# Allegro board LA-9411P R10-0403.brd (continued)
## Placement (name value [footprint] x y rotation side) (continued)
CH25  -  [C_0402]  206.75 72.14 315 top
CH26  -  [C_0603]  208.25 84.93 45 top
CH27  -  [C_0402]  211.6 71.87 315 top
CH28  -  [C_0805]  202.9 86.85 225 top
CH29  -  [C_0402]  209.92 68.98 135 top
CH30  -  [C_0402]  207.61 69.22 315 top
CH31  -  [C_0603]  200.86 78.49 315 top
CH32  -  [C_0603]  196.21 83.14 135 top
CH33  -  [C_0603]  195 81.92 135 top
CH34  -  [C_0402]  205.13 71.71 315 top
CH35  -  [C_0402]  210.99 72.48 135 top
CH36  -  [C_0402]  207.93 79.97 315 top
CH37  -  [C_0402]  207.31 74.01 135 top
CH38  -  [C_0603]  209.01 92.86 135 bottom
CH39  -  [C_0402]  201.92 66.02 135 top
CH40  -  [C_0402]  212.3 63.19 135 top
CH41  -  [C_0603]  205.26 81.24 135 top
CH42  -  [C_0402]  207.61 75.96 315 top
CH43  -  [C_0402]  208.66 70.24 135 top
CH44  -  [C_0402]  215.18 60.46 315 bottom
CH45  -  [C_0402]  209.38 71.86 135 top
CH46  -  [C_0402]  204.98 69.63 225 top
CH47  -  [C_0402]  215.47 77.24 45 top
CH48  -  [C_0402]  211.35 68.8 135 top
CH49  -  [C_0402]  203.78 70.93 315 top
CH50  -  [C_0402]  205.09 75.13 45 top
CH51  -  [C_0402]  209.83 61.91 225 top
CH52  -  [C_0603]  195.13 83.21 135 bottom
CH53  -  [C_0402]  212.27 80.59 135 top
CH54  -  [C_0402]  207.29 67.35 135 top
CH55  -  [C_0402]  211.58 55.31 225 bottom
CH56  -  [C_0402]  210.95 55.93 225 bottom
CH57  -  [C_0402]  210.32 56.56 225 bottom
CH58  -  [C_0402]  214.86 78.05 135 top
CH59  -  [C_0402]  202.62 67.19 45 top
CH60  -  [C_0402]  197.84 67.61 225 top
CH61  -  [C_0402]  198.72 69.29 315 top
CH62  -  [C_0402]  198.42 68.35 315 top
CH63  -  [C_0603]  211.3 88.21 135 bottom
CH64  -  [C_0402]  211.61 87.04 45 bottom
CH65  -  [C_0402]  208.49 77.42 135 top
CH66  -  [C_0402]  217.44 63.07 45 top
CH67  -  [C_0402]  210.03 75.69 315 top
CH68  -  [C_0402]  213.54 80.54 315 top
CH69  -  [C_0402]  209.78 73.79 135 top
CH70  -  [C_0402]  212.91 79.91 315 top
CH71  -  [C_0402]  211.2 75.94 45 top
CH72  -  [C_0402]  212.24 73.49 135 top
CH73  -  [C_0402]  211.26 70.15 135 top
CH74  -  [C_0402]  212.98 72.95 315 top
CH75  -  [C_0402]  215.8 68.15 225 top
CH76  -  [C_0402]  225.73 72.46 135 bottom
CH77  -  [C_0402]  225.22 67.77 225 bottom
CH78  -  [C_0402]  225.22 70.43 135 bottom
CH79  -  [C_0402]  227.12 66.02 315 top
CH80  -  [C_0402]  227.08 67.52 315 top
CLIP1  -  [EMI-110X138]  145.4 13.22 270 bottom
CMOS1  -  [SHORTPADS]  210.85 58.98 315 top
CV1  -  [C_0402]  217.6 109.44 270 top
CV2  -  [C_0402]  218.61 109.45 270 top
CV3  -  [C_0402]  217.98 105.99 270 top
CV4  -  [C_0402]  216.96 105.98 270 top
CV5  -  [C_0402]  213.66 105.98 270 top
CV6  -  [C_0402]  214.68 105.99 270 top
CV7  -  [C_0402]  213.66 109.44 270 top
CV8  -  [C_0402]  212.64 109.44 270 top
CV9  -  [C_0402]  211.37 105.99 270 top
CV10  -  [C_0402]  210.36 105.98 270 top
CV11  -  [C_0402]  210.36 109.44 270 top
CV12  -  [C_0402]  209.34 109.44 270 top
CV13  -  [C_0402]  195.5 161.92 180 top
CV14  -  [C_0402]  208.1 105.99 270 top
CV15  -  [C_0402]  207.06 105.98 270 top
CV16  -  [C_0402]  207.06 109.44 270 top
CV17  -  [C_0402]  206.04 109.44 270 top
CV18  -  [C_0402]  194.59 160.91 0 top
CV19  -  [C_0402]  216.98 158.13 180 top
CV20  -  [C_0402]  216.06 159.14 0 top
CV21  -  [C_0402]  210.42 151.83 90 top
CV22  -  [C_0402]  209.41 152.74 270 top
CV23  -  [C_0402]  216.06 163.21 0 top
CV24  -  [C_0402]  216.98 162.19 180 top
CV25  -  [C_0402]  196.45 170.12 90 top
CV26  -  [C_0402]  197.47 171.03 270 top
CV27  -  [C_0402]  206.36 152.74 270 top
CV28  -  [C_0402]  205.34 151.83 90 top
CV29  -  [C_0402]  227.95 170.12 90 bottom
CV30  -  [C_0402]  228.96 171.03 270 bottom
CV31  -  [C_0402]  214.99 170.12 90 bottom
CV32  -  [C_0402]  217.03 171.03 270 bottom
CV33  -  [C_0402]  231.25 152.74 270 top
CV34  -  [C_0402]  230.23 151.83 90 top
CV35  -  [C_0402]  216.98 154.06 180 top
CV36  -  [C_0402]  216.06 155.08 0 top
CV37  -  [C_0402]  236.08 150.2 270 bottom
CV38  -  [C_0402]  237.09 149.29 90 bottom
CV39  -  [C_0402]  227.69 170.12 90 top
CV40  -  [C_0402]  226.68 171.03 270 top
CV41  -  [C_0603]  184.45 109.6 180 top
CV42  -  [C_0603]  184.7 111.39 180 bottom
CV43  -  [C_0603]  183.85 132.47 180 bottom
CV44  -  [C_0603]  183.75 131.97 180 top
CV45  -  [C_0603]  213.88 171.51 270 bottom
CV46  -  [C_0603]  200.1 170.27 0 top
CV47  -  [C_0603]  232.77 170.13 90 bottom
CV48  -  [C_0603]  233.03 170.13 90 top
CV49  -  [C_0402]  227.99 129.22 180 top
CV50  -  [C_0402]  228.59 128.35 270 top
CV51  -  [C_0402]  229.47 119.21 270 top
CV52  -  [C_0402]  248.83 116.98 0 top
CV53  -  [C_0402]  246.95 111.14 180 top
CV54  -  [C_0402]  240.9 127.85 270 top
CV55  -  [C_0402]  227.04 127.26 180 top
CV56  -  [C_0603]  239.63 127.84 270 top
CV57  -  [C_0402]  249.74 110.38 180 top
CV58  -  [C_0402]  241.36 113.68 180 top
CV59  -  [C_0603]  241.35 112.41 180 top
CV60  -  [C_0402]  227.16 137.3 0 top
CV61  -  [C_0402]  227.09 136.07 0 top
CV62  -  [C_0603]  239.7 135.01 0 bottom
CV63  -  [C_0402]  227.44 119.21 270 top
CV64  -  [C_0603]  235.31 115.14 270 top
CV65  -  [C_0402]  228.46 119.21 270 top
CV66  -  [C_0402]  212.2 123.02 270 top
CV67  -  [C_0402]  216.14 125.22 0 top
CV68  -  [C_0402]  215.85 123.9 270 top
CV69  -  [C_0402]  232.59 121.05 90 top
CV70  -  [C_0402]  217.91 125.09 0 top
CV71  -  [C_0402]  217.92 126.01 90 top
CV72  -  [C_0402]  214.97 123.88 180 top
CV73  -  [C_0603]  208.9 125.93 90 top
CV74  -  [C_0603]  208.9 124.79 270 top
CV81  -  [C_0402]  231.29 138.51 0 top
CV82  -  [C_0402]  230.35 137.89 90 top
CV87  -  [C_0402]  242.73 134.76 0 bottom
CV92  -  [C_0402]  234.3 114.64 270 bottom
CV93  -  [C_0402]  229.54 120.99 90 top
CV94  -  [C_0402]  241.65 121.02 90 bottom
CV95  -  [C_0402]  239.73 121.93 90 bottom
CV98  -  [C_0603]  235.39 114.63 270 bottom
CV113  -  [C_0603]  235.84 120.57 0 top
CV114  -  [C_0402]  233.47 122.32 90 top
CV115  -  [C_0402]  246.03 137.81 0 bottom
CV116  -  [C_0402]  225.97 123.92 180 top
CV117  -  [C_0402]  224.85 121.84 270 top
CV118  -  [C_0402]  232.57 119.27 0 top
CV119  -  [C_0402]  232.57 118.25 0 top
CV129  -  [C_0402]  187.56 106.87 90 top
CV130  -  [C_0402]  183.7 129.68 180 bottom
CV131  -  [C_0402]  185.78 111.59 270 bottom
CV133  -  [C_0402]  183.7 142.89 180 top
CV134  -  [C_0402]  194.1 129.68 90 bottom
CV135  -  [C_0402]  203.31 170.12 90 bottom
CV137  -  [C_0402]  183.7 127.65 180 bottom
CV138  -  [C_0402]  183.88 110.63 180 top
CV139  -  [C_0402]  203.11 118.25 0 top
CV140  -  [C_0402]  187.82 111.59 270 bottom
CV141  -  [C_0402]  183.7 130.7 180 bottom
CV142  -  [C_0402]  186.8 111.59 270 bottom
CV143  -  [C_0402]  187.05 130.64 270 bottom
CV144  -  [C_0402]  183.7 135.01 180 top
CV145  -  [C_0402]  185.68 148.02 90 top
CV146  -  [C_0402]  183.7 143.9 180 top
CV147  -  [C_0402]  183.75 133.11 180 top
CV148  -  [C_0402]  192.13 130.64 270 bottom
CV149  -  [C_0402]  196.2 130.64 270 bottom
CV150  -  [C_0402]  195.18 130.64 270 bottom
CV151  -  [C_0402]  201.02 111.59 270 bottom
CV152  -  [C_0402]  183.7 128.66 180 bottom
CV153  -  [C_0402]  183.88 111.65 180 top
CV154  -  [C_0402]  183.68 130.7 180 top
CV155  -  [C_0402]  203.11 119.27 0 top
CV156  -  [C_0402]  183.7 133.74 180 bottom
CV157  -  [C_0402]  183.7 142.89 180 bottom
CV158  -  [C_0402]  183.7 143.9 180 bottom
CV159  -  [C_0402]  183.7 136.03 180 top
CV162  -  [C_0402]  193.09 129.68 90 bottom
CV163  -  [C_0402]  214.5 139.34 0 top
CV168  -  [C_0402]  217.85 137.46 0 top
CV170  -  [C_0402]  218.03 138.36 90 top
CV173  -  [C_0603]  204.96 112.65 180 bottom
CV176  -  [C_0402]  183.7 134 180 top
CV177  -  [C_0402]  183.68 129.68 180 top
CV178  -  [C_0402]  183.7 128.66 180 top
CV179  -  [C_0402]  202.04 111.59 270 bottom
CV180  -  [C_0402]  197.21 130.64 270 bottom
CV181  -  [C_0402]  191.12 130.64 270 bottom
CV182  -  [C_0402]  203.11 120.28 0 top
CV185  -  [C_0402]  199.25 130.64 270 bottom
CV188  -  [C_0402]  185.78 111.59 270 top
CV189  -  [C_0402]  188.07 130.64 270 bottom
CV191  -  [C_0402]  183.7 144.92 180 top
CV192  -  [C_0402]  184.77 148.02 90 top
CV198  -  [C_0402]  231.3 113.68 0 bottom
CV199  -  [C_0402]  216.06 165.24 0 top
CV200  -  [C_0402]  206.36 170.12 90 bottom
CV201  -  [C_0603]  234.04 115.14 270 top
CV202  -  [C_0402]  205.34 170.12 90 bottom
CV203  -  [C_0402]  231.3 114.69 0 bottom
CV204  -  [C_0402]  234.87 137.79 90 top
CV206  -  [C_0603]  237.35 137.74 90 top
CV207  -  [C_0402]  183.7 124.6 180 bottom
CV208  -  [C_0402]  190.86 110.68 90 bottom
CV209  -  [C_0402]  182.79 139.84 0 top
CV210  -  [C_0402]  183.7 140.86 180 top
CV211  -  [C_0402]  235.76 137.79 90 top
CV212  -  [C_0603]  201.63 109.22 0 bottom
CV213  -  [C_0402]  234.36 120.67 90 top
CV214  -  [C_0402]  220.79 125.11 180 top
CV215  -  [C_0402]  206.56 142.89 180 top
CV216  -  [C_0603]  206.8 144.16 180 top
CV217  -  [C_0603]  204.96 111.38 180 bottom
CV218  -  [C_0402]  216.24 128.79 180 top
CV219  -  [C_0402]  213.89 142.6 0 top
CV220  -  [C_0402]  239.43 138.82 0 top
CV221  -  [C_0603]  239.44 136.54 0 top
CV222  -  [C_0402]  239.43 137.81 0 top
CV223  -  [C_0402]  237.16 140.31 90 top
CV224  -  [C_0603]  239.3 140.35 90 top
CV225  -  [C_0402]  238.15 140.31 90 top
CV226  -  [C_0603]  231.06 111.9 0 bottom
CV227  -  [C_0603]  231.06 110.63 0 bottom
CV237  -  [C_0402]  222.45 140.15 90 top
CV238  -  [C_0603]  204.96 113.92 180 bottom
CV274  -  [C_0603]  215.31 132.6 0 top
CV275  -  [C_0603]  215.31 133.87 0 top
CV278  -  [C_0402]  224 137.26 270 top
CV279  -  [C_0402]  221.01 138.12 180 top
CV280  -  [C_0402]  216.98 170.57 180 top
CV281  -  [C_0402]  209.41 170.12 90 top
CV283  -  [C_0402]  207.22 170.12 90 top
CV284  -  [C_0402]  203.36 170.24 180 top
CV285  -  [C_0402]  209.41 171.03 270 bottom
CV286  -  [C_0402]  201.28 171.03 270 bottom
CV287  -  [C_0402]  204.33 170.12 90 bottom
CV288  -  [C_0402]  202.32 170.12 90 bottom
CV290  -  [C_0402]  211.44 170.12 90 bottom
CV291  -  [C_0402]  212.71 171.03 270 bottom
CV292  -  [C_0402]  210.42 171.03 270 bottom
CV293  -  [C_0402]  216.06 166.51 0 top
CV294  -  [C_0402]  205.19 170.12 90 top
CV295  -  [C_0402]  213.47 170.12 90 top
CV296  -  [C_0402]  214.49 170.12 90 top
CV297  -  [C_0402]  211.44 170.12 90 top
CV298  -  [C_0402]  230.23 152.74 270 bottom
CV299  -  [C_0402]  231 170.12 90 bottom
CV301  -  [C_0402]  231.76 170.12 90 top
CV302  -  [C_0402]  229.98 170.12 90 bottom
CV303  -  [C_0402]  223.88 171.03 270 bottom
CV304  -  [C_0402]  216.98 168.54 180 top
CV305  -  [C_0402]  225.66 152.74 270 top
CV306  -  [C_0402]  232.27 152.74 270 bottom
CV307  -  [C_0402]  216.98 167.53 180 top
CV308  -  [C_0402]  233.28 152.74 270 bottom
CV309  -  [C_0402]  234.3 152.74 270 top
CV310  -  [C_0402]  216.98 169.56 180 top
CV311  -  [C_0402]  222.87 170.12 90 bottom
CV312  -  [C_0402]  221.85 170.12 90 bottom
CV313  -  [C_0402]  234.3 152.74 270 bottom
CV315  -  [C_0402]  231.28 152.73 270 bottom
CV316  -  [C_0402]  233.28 152.74 270 top
CV318  -  [C_0402]  221.85 152.72 270 top
CV319  -  [C_0402]  223.18 152.69 270 top
CV320  -  [C_0402]  236.08 152.74 270 bottom
CV322  -  [C_0402]  182.79 123.58 0 bottom
CV323  -  [C_0402]  204.82 116.13 180 bottom
CV324  -  [C_0402]  203.91 117.14 0 bottom
CV325  -  [C_0402]  204.02 122.31 180 top
CV326  -  [C_0402]  191.88 111.59 270 bottom
CV327  -  [C_0402]  203.11 123.33 0 top
CV328  -  [C_0402]  196.96 110.68 90 bottom
CV329  -  [C_0402]  195.94 111.59 270 bottom
CV330  -  [C_0402]  182.79 124.6 0 top
CV331  -  [C_0402]  183.7 125.62 180 top
CV332  -  [C_0402]  202.95 141.33 0 top
CV333  -  [C_0402]  203.87 144.37 180 top
CV340  -  [C_0402]  235.11 126.89 0 top
CV341  -  [C_0402]  223.88 115.51 90 top
CV342  -  [C_0402]  235.11 123.84 0 top
CV343  -  [C_0402]  226.06 139.39 90 top
CV349  -  [C_0402]  183.7 146.95 180 bottom
CV350  -  [C_0402]  182.79 145.94 0 bottom
CV351  -  [C_0402]  203.02 139.81 0 bottom
CV352  -  [C_0402]  203.93 138.8 180 bottom
CV353  -  [C_0402]  183.7 147.97 180 top
CV354  -  [C_0402]  182.79 148.98 0 top
CV355  -  [C_0402]  183.7 141.87 180 bottom
CV356  -  [C_0402]  182.79 138.82 0 bottom
CV357  -  [C_0402]  236.13 118.76 0 top
CV358  -  [C_0402]  243.42 136.13 90 top
D1  -  [RB751V40_SC76-2]  120.51 93.19 270 bottom
D2  -  [RB751VM-40TE-17_SOD323-2]  24.24 193.47 270 top
D8  -  [L30ESDL5V0C3-2_SOT23-3]  191.64 160.3 0 top
D11  -  [RB751VM-40TE-17_SOD323-2]  348.37 169.35 90 bottom
D12  -  [RB751VM-40TE-17_SOD323-2]  346.69 169.35 90 bottom
D23  -  [L30ESDL5V0C3-2_SOT23-3]  341.23 201.66 270 top
D31  -  [RB751V40_SC76-2]  259.95 174.3 90 bottom
D32  -  [RB751V40_SC76-2]  219.06 184.57 90 bottom
D33  -  [L30ESD24VC3-2_SOT23-3]  197.98 179.18 0 top
D35  -  [RB751V40_SC76-2]  267.83 172.52 90 bottom
D36  -  [RB751V40_SC76-2]  281.98 182.4 180 bottom
D37  -  [L30ESDL5V0C3-2_SOT23-3]  262.73 98.32 90 top
D59  -  [RB751V40_SC76-2]  330.48 157.11 0 top
D62  -  [RB751V40_SC76-2]  331.16 161.68 180 top
D64  -  [RB751V40_SC76-2]  182.4 151.81 0 bottom
D65  -  [RB751V40_SC76-2]  171.73 158.38 0 top
D66  -  [RB751V40_SC76-2]  181.64 154.06 0 top
D68  -  [RB751V40_SC76-2]  181.64 155.84 0 top
D69  -  [RB751V40_SC76-2]  182.4 153.59 0 bottom
D71  -  [RB751V40_SC76-2]  242.34 120.54 0 top
D72  -  [L30ESDL5V0C3-2_SOT23-3]  324.47 222.43 90 bottom
D73  -  [RB751V40_SC76-2]  171.73 160.16 0 top
D74  -  [L30ESDL5V0C3-2_SOT23-3]  21.98 180.99 270 bottom
D78  -  [IP4292CZ10-TBR_XSON10_2P5X1]  330.55 222.09 180 bottom
D79  -  [IP4292CZ10-TBR_XSON10_2P5X1]  22 185.8 270 bottom
D81  -  [L03ESDL5V0CC3-2_SOT23-3]  352.64 180.48 90 bottom
D82  -  [L03ESDL5V0CC3-2_SOT23-3]  352.64 171.84 90 bottom
D83  -  [L03ESDL5V0CC3-2_SOT23-3]  353.91 175.12 180 bottom
D88  -  [IP4292CZ10-TBR_XSON10_2P5X1]  352.58 219.71 270 bottom
D89  -  [L30ESDL5V0C3-2_SOT23-3]  350.5 215.15 90 bottom
D90  -  [L30ESDL5V0C3-2_SOT23-3]  352.69 191.4 270 bottom
D91  -  [IP4292CZ10-TBR_XSON10_2P5X1]  352.96 196.21 270 bottom
FD1  -  [FIDUCIAL_C40M80]  277.73 16.14 0 top
FD2  -  [FIDUCIAL_C40M80]  275.7 18.55 180 bottom
FD3  -  [FIDUCIAL_C40M80]  24.24 215.79 0 top
FD4  -  [FIDUCIAL_C40M80]  24.24 215.79 180 bottom
H1  -  [H_2P8]  66 186.6 0 top
H2  -  [H_6P2]  301 60.27 0 top
H3  -  [H_2P8]  111.33 21.17 0 top
H4  -  [H_2P8]  111.33 72.31 0 top
H5  -  [H_2P8]  282 9.36 0 top
H6  -  [H_2P8]  111.33 14.36 0 top
H7  -  [H_2P8]  206 3.56 0 top
H8  -  [H_2P8]  102 93.7 0 top
H9  -  [H_2P8]  232.8 77.1 0 top
H10  -  [H_2P8]  248 126.6 0 top
H11  -  [H_2P8]  362 163.56 0 top
H12  -  [H_2P8]  230 184.81 0 top
H13  -  [H_2P8]  142 184.81 0 top
H14  -  [H_2P3]  112.41 143.83 0 top
H15  -  [H_2P3]  184.01 162.93 0 top
H16  -  [H_3P5]  129.05 112.6 0 top
H17  -  [H_3P5]  129.05 76.6 0 top
H18  -  [H_3P5]  180.21 118.1 0 top
H19  -  [H_3P5]  181.05 81.1 0 top
H20  -  [H_2P3]  287.7 41.56 0 top
H21  -  [H_2P5X8P0]  344 153.56 90 top
H22  -  [H_4P8]  317.9 224.56 0 top
H23  -  [H_3P5]  242.8 151.5 0 top
H24  -  [H_3P5]  191 153.04 0 top
H25  -  [H_3P5]  225.22 108.5 0 top
H26  -  [H_2P8]  11 170.86 180 bottom
H27  -  [H_2P8]  17 216.04 180 bottom
H28  -  [H_3P8]  65 202.06 180 bottom
H29  -  [H_3P8]  45 202.06 180 bottom
H30  -  [H_2P3]  287.7 20.56 0 top
JAPS1  -  [TYCO_1-2041070-6_16P]  303.26 110.94 270 top
JBTB1  -  [E-T_1001K-F30C-02L_30P-T]  58.56 204.48 0 top
JCAM1  -  [PS_HPW10003-08MR2_8P]  195.45 167.06 270 bottom
JCPU1  -  [LOTES_AZIF0012-P002B_947P-T]  172.2 79.45 180 bottom
JDEG2  -  [TYCO_1-2041070-0_10P]  327.47 165.46 90 bottom
JDIMM1  -  [TYCO_2-2013290-1_204P]  122.9 39.1 180 bottom
JDIMM2  -  [TYCO_2-2013311-1_204P]  122.9 26.1 180 bottom
JDOCK1  -  [JAE_WD2F144WB1R300_144P]  167.25 180.81 0 bottom
JEXP1  -  [E-T_1001K-F30C-02L_30P-T]  289.6 27.5 270 top
JFAN1  -  [ACES_50273-0040N-001_4P]  111.8 94.92 254.2 bottom
JHDMI1  -  [CONCR_099AKAC19NBLCNF_19P-T]  10.05 200.59 90 bottom
JHP1  -  [SINGA_2SJ3080-001111F_6P-T]  360.42 182.91 90 bottom
JKB1  -  [ACES_51524-01001-003_10P]  315.9 138.62 270 top
JLED2  -  [PS_HPF05052-061000R_6P]  327.33 169.95 180 top
JLOM1  -  [TE_2041528-1_13P-T]  300.93 227.16 0 bottom
JLVDS1  -  [ACES_59003-04006-001_40P]  175.91 147.97 270 bottom
JMDC1  -  [ACES_50124-0127N-001_12P]  259.14 139.8 90 bottom
JMINI1  -  [BELLW_80003-7041_52P]  326.15 211.15 0 bottom
JMINI2  -  [BELLW_80003-7041_52P]  251.05 187.36 0 bottom
JMINI3  -  [BELLW_80003-7041_52P]  294.26 184.81 0 bottom
JRTC1  -  [ACES_50273-0020N-001_2P]  322.08 151.3 180 bottom
JSATA1  -  [SANTA_196003-1_22P]  112.28 63.21 90 bottom
JSATA2  -  [TYCO_2-2129116-3_31P-T]  233.93 27.23 270 bottom
JSD1  -  [T-SOL_156-1000302606_18P-T]  267.85 29.42 0 top
JSF1  -  [PS_HPF10052-04M000R_4P]  323.28 145.66 180 top
JSIM1  -  [T-SOL_159-1000302602_10P-T]  247.04 177.01 180 top
JSPI1  -  [TYCO_2-2041070-0_20P-T]  209.68 40.4 0 bottom
JSPK1  -  [ACES_50279-0040N-001_4P]  114.66 8.45 270 top
JTAG1  -  [SHORTPADS]  288.16 99.12 270 top
JTP1  -  [PS_HPF05052-081000R_8P]  256.95 99.03 270 top
JUSB1  -  [SANTA_373130-1_9P]  332.95 226.01 0 bottom
JUSB2  -  [SANTA_373130-1_9P]  357.21 216.31 270 bottom
JUSB3  -  [SANTA_373130-1_9P]  357.21 192.81 270 bottom
JUSB4  -  [SANTA_373130-1_9P]  14.79 186.6 90 bottom
JUSH1  -  [TYCO_2-2041070-0_20P-T]  263.95 89.07 90 top
JXDP1  -  [SAMTE_BSH-030-01-L-D-A_60P]  113.83 104.4 90 bottom
JXDP2  -  [SAMTE_BSH-030-01-L-D-A_60P]  276.33 91.33 270 bottom
L1  -  [MURAT_DLW21SN900HQ2L_0805_4P]  18.99 204.44 180 bottom
L2  -  [MURAT_DLW21SN900HQ2L_0805_4P]  18.99 206.72 180 bottom
L3  -  [MURAT_DLW21SN900HQ2L_0805_4P]  18.99 201.64 180 bottom
L4  -  [MURAT_DLW21SN900HQ2L_0805_4P]  18.99 199.1 180 bottom
L10  -  [MURAT_DLW21SN121SQ2L_4P]  190.4 167.89 270 bottom
L29  -  [TAIYO_CBC2012T4R7M_2P]  314.05 193.42 270 bottom
L45  -  [MURAT_BLM18BD601SN1D_2P]  249.9 52.97 0 top
L47  -  [MURAT_BLM18BD601SN1D_2P]  252.06 37.62 0 top
L51  -  [MURAT_DLW21SN900SQ2L_0805_4P]  325.57 217.73 90 bottom
L77  -  [MURAT_BLM21PG600SN1D_L0805_2P]  345.68 180.92 180 bottom
L90  -  [MURAT_DLW21SN900SQ2L_0805_4P]  26.11 180.56 180 bottom
L95  -  [MURAT_DLW21SN900HQ2L_0805_4P]  327.85 217.73 90 bottom
L96  -  [MURAT_DLW21SN900HQ2L_0805_4P]  329.89 218.75 90 bottom
L97  -  [MURAT_DLW21SN900HQ2L_0805_4P]  26.11 185.39 180 bottom
L98  -  [MURAT_DLW21SN900HQ2L_0805_4P]  26.11 183.36 180 bottom
L99  -  [MURAT_DLW21SN900HQ2L_0805_4P]  187.86 184.2 90 top
L107  -  [MURAT_DLW21SN900SQ2L_0805_4P]  346.88 215.7 0 bottom
L108  -  [MURAT_DLW21SN900HQ2L_0805_4P]  347.75 219.64 0 bottom
L109  -  [MURAT_DLW21SN900HQ2L_0805_4P]  347.75 217.73 0 bottom
L110  -  [MURAT_DLW21SN900SQ2L_0805_4P]  349.19 186.74 90 bottom
L111  -  [MURAT_DLW21SN900HQ2L_0805_4P]  348.51 196.91 0 bottom
L112  -  [MURAT_DLW21SN900HQ2L_0805_4P]  348.51 194.87 0 bottom
L113  -  [CHILI_PBY160808T-300Y-N_2P]  343.54 177.52 90 top
L114  -  [CHILI_PBY160808T-300Y-N_2P]  342.06 177.53 90 top
L115  -  [CHILI_PBY160808T-300Y-N_2P]  339.01 177.52 90 top
L116  -  [CHILI_PBY160808T-300Y-N_2P]  340.51 177.52 90 top
LE2  -  [MURAT_DLW21SN900HQ2L_0805_4P]  250.38 35.79 270 top
LE3  -  [MURAT_BLM18BB221SN1D_2P]  334.97 173.88 180 top
LE4  -  [MURAT_DLW21SN900HQ2L_0805_4P]  252.42 35.79 270 top
LE5  -  [MURAT_DLW21SN900HQ2L_0805_4P]  248.35 35.79 270 top
LED1  -  [LED_LTW-193ZDS5_2P]  340.5 213.56 270 top
LH1  -  [MURAT_BLM18PG181SN1D_L0603_2P]  222.72 81 225 top
LV16  -  [R_0402]  237.09 113.73 90 bottom
LV17  -  [R_0402]  206.56 141.87 180 top
LV18  -  [R_0402]  239.43 135.27 0 top
LV19  -  [R_0402]  238.41 128.92 0 top
LV20  -  [R_0402]  240.6 133.74 180 bottom
LV21  -  [R_0402]  240.52 140.49 90 top
LV30  -  [R_0402]  243.19 113.37 270 top
MBATT1  -  [OCTEK_BTJ-06LDFB_6P]  232.88 64.51 270 bottom
ME1  -  [SHORTPADS]  212.47 57.36 135 top
NOREF  -  []  184.01 162.93 0 top
NOREF#2  -  []  142 184.81 0 top
NOREF#3  -  []  235.31 17.21 0 top
NOREF#4  -  []  65 202.06 90 top
NOREF#5  -  []  317.9 224.56 0 top
NOREF#6  -  []  17 216.04 0 top
NOREF#7  -  []  282 9.36 0 top
NOREF#8  -  []  129.05 76.6 0 top
NOREF#9  -  []  301 60.27 0 top
NOREF#10  -  []  362 163.56 0 top
NOREF#11  -  []  287.7 20.56 0 top
NOREF#12  -  []  230 184.81 0 top
NOREF#13  -  []  206 3.56 0 top
NOREF#14  -  []  111.33 14.36 0 top
NOREF#15  -  []  66 186.6 0 top
NOREF#16  -  []  344 153.56 0 top
NOREF#17  -  []  267.57 163.47 0 top
NOREF#18  -  []  248 126.6 0 top
NOREF#19  -  []  232.8 77.1 0 top
NOREF#20  -  []  45 202.06 270 top
NOREF#21  -  []  11 170.86 0 top
NOREF#22  -  []  148.95 57.4 0 top
NOREF#23  -  []  111.33 72.31 0 top
NOREF#24  -  []  287.7 41.56 0 top
NOREF#25  -  []  111.33 21.17 0 top
NOREF#26  -  []  181.05 81.1 0 top
NOREF#27  -  []  112.41 143.83 0 top
NOREF#28  -  []  102 93.7 180 top
NOREF#29  -  []  263.65 167.35 270 top
NOREF#30  -  []  225.22 108.5 0 top
NOREF#31  -  []  129.05 112.6 0 top
NOREF#32  -  []  180.2 118.11 0 top
NOREF#33  -  []  242.8 151.5 0 top
NOREF#34  -  []  205.47 96.23 0 top
NOREF#35  -  []  126.98 -36.94 0 top
NOREF#36  -  []  191 153.04 0 top
NOREF#37  -  []  268.33 15.75 180 bottom
NOREF#38  -  []  170.86 59.63 180 bottom
NOREF#39  -  []  272.4 22.06 180 bottom
PBATT1  -  [OCTEK_BTJ-09WKFB_9P]  110.25 189.4 0 bottom
PC1  -  [C_0603]  237.98 73.8 270 top
PC2  -  [C_0402]  240.1 71.98 180 top
PC3  -  [C_0603]  327.13 154.66 0 bottom
PC4  -  [C_0603]  125.78 186.07 180 top
PC5  -  [C_0402]  125.54 183.53 180 top
PC6  -  [C_0603]  124.77 7 0 top
PC7  -  [C_0603]  127.94 2.17 0 top
PC8  -  [C_0805]  131.34 169.94 0 top
PC9  -  [C_0603]  125.71 164.54 270 top
PC10  -  [C_0603]  124.44 164.54 270 top
PC11  -  [C_0603]  123.17 164.54 270 top
PC12  -  [C_0603]  138.92 177.49 90 top
PC13  -  [C_0805]  127.24 164.44 270 top
PC14  -  [C_0603]  137.84 166 0 top
PC15  -  [C_0402]  128.05 3.31 0 top
PC16  -  [C_0603]  140.32 177.49 90 top
PC17  -  [C_0402]  106.46 180.95 0 top
PC101  -  [C_MP6VL220MC6]  131.18 11.32 180 bottom
PC102  -  [C_MP6VL220MC6]  168.89 7.92 90 bottom
PC103  -  [C_0402]  162.62 10.05 180 top
PC104  -  [C_0805]  163.01 11.57 180 top
PC105  -  [C_0402]  139 8.39 180 top
PC106  -  [C_0402]  139 7.38 180 top
PC107  -  [C_0805]  139.39 9.79 180 top
PC108  -  [C_0402]  162.62 9.03 180 top
PC109  -  [C_0805]  163.01 13.35 180 top
PC110  -  [C_0805]  139.39 11.57 180 top
PC111  -  [C_0603]  155.18 6.31 180 bottom
PC112  -  [C_0603]  146.35 7.51 180 bottom
PC114  -  [C_0603]  151.68 4.97 180 top
PC116  -  [C_0603]  134.03 7.51 0 top
PC117  -  [C_0603]  149.46 10.11 90 bottom
PC118  -  [C_0603]  150.73 10.11 90 bottom
PC119  -  [C_0603]  157.21 8.84 90 top
PC120  -  [C_0603]  146.35 3.95 180 bottom
PC201  -  [C_MP2VU390MC5R7]  179.5 7.99 270 bottom
PC202  -  [C_0805]  196.29 15.89 180 top
PC203  -  [C_0805]  196.29 17.67 180 top
PC204  -  [C_0402]  195.89 13.35 180 top
PC205  -  [C_0402]  195.89 14.36 180 top
PC206  -  [C_0603]  206.55 15.13 180 top
PC207  -  [C_0805]  206.1 12.42 270 bottom
PC208  -  [C_0805]  206.1 12.42 270 top
PC209  -  [C_0402]  210.93 10.25 270 top
PC210  -  [C_0603]  208.14 19.13 270 top
PC211  -  [C_0402]  214.28 11.06 0 top
PC212  -  [C_0603]  192.83 13.73 180 bottom
PC213  -  [C_0603]  210.93 17.73 90 top
PC214  -  [C_0402]  211.95 10.25 270 top
PC215  -  [C_0402]  214.28 14.11 0 top
PC216  -  [C_D2]  177.55 12.59 180 top
PC301  -  [C_MP2VU390MC5R7]  220.84 11.32 0 bottom
PC302  -  [C_0402]  227.82 8.22 270 top
PC303  -  [C_0402]  226.8 8.22 270 top
PC304  -  [C_0805]  223.5 8.36 270 top
PC305  -  [C_0805]  225.28 8.36 270 top
PC306  -  [C_0603]  239.12 12.2 90 top
PC307  -  [C_0402]  239.12 4.91 270 top
PC308  -  [C_0603]  240.65 12.2 90 top
PC309  -  [C_0603]  227.39 3.44 180 bottom
PC400  -  [C_0805]  231.29 102.12 0 top
PC401  -  [C_0402]  231.71 103.77 180 top
PC402  -  [C_0402]  230.79 105.04 0 top
PC403  -  [C_0805]  239.89 101.07 270 top
PC404  -  [C_0805]  238.11 101.07 270 top
PC405  -  [C_0402]  241.41 101.18 270 top
PC406  -  [C_0402]  232.27 107.38 90 top
PC407  -  [C_0402]  241.97 108.34 0 top
PC500  -  [C_0402]  114.71 153.94 0 bottom
PC501  -  [C_0603]  161.59 152.29 180 top
PC502  -  [C_0603]  157.21 154.13 270 top
PC503  -  [C_0805]  151.62 145.34 90 top
PC504  -  [C_0402]  153.02 145.73 90 top
PC505  -  [C_0805]  149.84 145.34 90 top
PC506  -  [C_0805]  155.94 145.34 90 top
PC507  -  [C_0402]  157.34 145.73 90 top
PC508  -  [C_0603]  148.45 141.55 90 bottom
PC509  -  [C_0603]  122.02 153.43 0 top
PC510  -  [C_0402]  113.34 155.97 180 bottom
PC511  -  [C_0603]  125.14 157.87 0 bottom
PC512  -  [C_0805]  129.65 144.96 90 top
PC513  -  [C_0805]  125.84 144.96 90 top
PC514  -  [C_0805]  124.06 144.96 90 top
PC515  -  [C_0402]  127.36 145.35 90 top
PC516  -  [C_0402]  131.05 145.22 90 top
PC517  -  [C_0402]  118.47 156.81 270 top
PC518  -  [C_0603]  121.78 156.79 270 top
PC519  -  [C_0402]  113.65 158 90 top
PC520  -  [C_0402]  115.17 162.9 270 bottom
PC521  -  [C_0402]  121.27 159.58 90 bottom
PC522  -  [C_0603]  123.43 148.67 90 bottom
PC523  -  [C_0402]  115.63 159.02 180 top
PC524  -  [C_0603]  122.16 141.55 90 bottom
PC525  -  [C_0402]  114.71 155.97 0 bottom
PC526  -  [C_0402]  112.43 156.98 0 bottom
PC527  -  [C_0402]  112.43 159.02 0 bottom
PC528  -  [C_0402]  122.41 160.49 270 bottom
PC529  -  [C_0603]  123.55 160.73 270 bottom
PC530  -  [C_EEEFK1E101YP]  141.08 155.8 270 bottom
PC531  -  [C_EEEFK1E101YP]  155.81 155.8 270 bottom
PC532  -  [C_EEEFK1E101YP]  148.45 155.8 270 bottom
PC533  -  [C_0805]  142.86 145.08 90 top
PC534  -  [C_0805]  138.67 145.08 90 top
PC535  -  [C_0805]  136.89 145.08 90 top
PC536  -  [C_0402]  140.06 145.48 90 top
PC537  -  [C_0402]  144.25 145.61 90 top
PC538  -  [C_0603]  123.55 160.73 270 top
PC539  -  [C_0402]  121.27 161.99 90 bottom
PC540  -  [C_0402]  119.24 160.49 270 bottom
PC541  -  [C_0402]  117.2 162.9 270 bottom
PC542  -  [C_0603]  126.54 154.19 180 bottom
PC543  -  [C_0603]  135.36 141.55 90 bottom
PC544  -  [C_0402]  118.22 160.49 270 bottom
PC545  -  [C_0402]  119.24 160.49 270 top
PC546  -  [C_0402]  120.51 155.89 90 top
PC547  -  [C_0402]  118.22 161.99 90 bottom
PC548  -  [C_0402]  115.27 149.11 90 bottom
PC600  -  [C_0402]  310.37 164.4 90 top
PC601  -  [C_0603]  298.12 160.67 0 top
PC602  -  [C_0402]  298.36 161.94 0 top
PC603  -  [C_0805]  298.17 165.24 0 top
PC604  -  [C_0805]  298.17 167.4 0 top
PC605  -  [C_0603]  303.2 163.72 0 bottom
PC606  -  [C_D2]  272.14 162.55 90 bottom
PC607  -  [C_0603]  298.75 171.34 0 bottom
PC608  -  [C_0603]  303.7 160.92 0 bottom
PC609  -  [C_0402]  317.66 162.7 0 bottom
PC610  -  [C_0603]  303.7 160.92 0 top
PC611  -  [C_0402]  315.37 162.7 0 top
PC612  -  [C_0402]  317.61 161.58 0 bottom
PC613  -  [C_0402]  315.37 161.68 0 top
PC614  -  [C_0402]  315.37 161.68 0 bottom
PC615  -  [C_0402]  312.59 154.52 270 bottom
PC616  -  [C_0402]  313.29 157.82 270 bottom
PC617  -  [C_0603]  310.18 160.22 90 top
PC618  -  [C_0603]  308.91 160.22 90 top
PC619  -  [C_0603]  297.86 149.49 0 top
PC620  -  [C_0402]  298.1 154.95 0 top
PC621  -  [C_0805]  297.89 151.29 0 top
PC622  -  [C_0805]  298.12 156.55 0 top
PC623  -  [C_0603]  303.7 159.65 0 bottom
PC624  -  [C_0402]  312.28 160.21 90 top
PC625  -  [C_0402]  310.62 156.91 90 top
PC626  -  [C_0603]  309.48 154.76 270 bottom
PC627  -  [C_0402]  311.64 154.52 270 top
PC628  -  [C_D2]  276.97 162.55 90 bottom
PC629  -  [C_D2]  276.97 156.25 270 bottom
PC630  -  [C_0402]  311.26 161.12 270 top
PC631  -  [C_0603]  294.37 146.98 0 bottom
PC632  -  [C_0402]  312.45 152.12 180 bottom
PC660  -  [C_0805]  196.29 97.42 180 top
PC661  -  [C_0805]  188.83 95.64 180 top
PC662  -  [C_0805]  188.83 90.31 180 top
PC663  -  [C_0805]  188.83 93.87 180 top
PC664  -  [C_0805]  188.83 92.09 180 top
PC665  -  [C_0402]  201.18 91.88 90 top
PC666  -  [C_0402]  197.72 96.96 90 top
PC667  -  [C_0402]  197.47 90.51 270 top
PC668  -  [C_0402]  199.75 97.88 270 top
PC669  -  [C_0805]  285.35 132.13 90 top
PC670  -  [C_0603]  286.88 132.16 90 top
PC671  -  [C_0402]  280.78 129.48 90 top
PC672  -  [C_0805]  288.65 139.04 270 top
PC673  -  [C_0805]  286.88 139.04 270 top
PC674  -  [C_0402]  279.76 129.48 90 top
PC675  -  [C_0402]  280.53 134.96 270 top
PC676  -  [C_0603]  280.53 139.65 270 top
PC677  -  [C_D2]  272.14 156.25 270 bottom
PC678  -  [C_0402]  311.89 157.04 90 top
PC679  -  [C_0402]  314.99 155.59 0 bottom
PC680  -  [C_0603]  196.13 97.42 180 bottom
PC700  -  [C_0603]  106.18 168.15 270 top
PC701  -  [C_0402]  97.01 180.05 270 top
PC702  -  [C_0603]  79.65 180.84 270 bottom
PC703  -  [C_0603]  78.34 185.74 90 bottom
PC704  -  [C_0402]  78.44 188.68 0 top
PC705  -  [C_0402]  79.4 186.65 270 bottom
PC706  -  [C_0603]  79.48 183.46 180 bottom
PC707  -  [C_0805]  82.32 185.81 0 top
PC708  -  [C_0402]  75.32 186.23 0 bottom
PC709  -  [C_0603]  83.87 184.04 180 top
PC710  -  [C_0402]  96.12 180.05 270 top
PC711  -  [C_0805]  81.15 180.97 270 bottom
PC712  -  [C_0805]  84.67 180.96 270 bottom
PC713  -  [C_0805]  86.39 180.96 270 bottom
PC714  -  [C_0805]  82.9 180.96 270 bottom
PC715  -  [C_0603]  99.07 172.12 180 bottom
PC716  -  [C_0402]  76.23 184.45 180 bottom
PC717  -  [C_0603]  116.7 174.07 270 top
PC718  -  [C_0805]  115.17 174.22 270 top
PC719  -  [C_0805]  113.39 174.22 270 top
PC720  -  [C_0603]  109.27 159.14 180 top
PC721  -  [C_0402]  77.33 180.94 270 bottom
PC722  -  [C_0402]  77.28 178.96 180 bottom
PC723  -  [C_0402]  76.31 180.02 90 bottom
PC724  -  [C_0402]  101.51 168.29 0 top
PC725  -  [C_0402]  101.51 168.29 0 bottom
PC726  -  [C_0402]  91.25 165.37 180 top
PC727  -  [C_0402]  91.25 164.48 180 top
PC728  -  [C_0402]  96.05 158.32 0 top
PC729  -  [C_0402]  101.51 162.19 0 bottom
PC730  -  [C_0402]  101.51 164.22 0 top
PC731  -  [C_0805]  112.47 174.26 270 bottom
PC732  -  [C_0805]  110.56 174.26 270 bottom
PC733  -  [C_0402]  89.24 162.79 180 top
PC734  -  [C_0805]  102.57 186.77 0 top
PC735  -  [C_0805]  102.57 188.56 0 top
PC736  -  [C_0805]  102.22 173 180 top
PC737  -  [C_0805]  102.22 174.77 180 top
PC738  -  [C_0805]  102.22 176.54 180 top
PC739  -  [C_0805]  86.39 180.96 270 top
PC740  -  [C_0805]  84.67 180.96 270 top
PC800  -  [C_0603]  243.95 73.29 0 top
PC801  -  [C_0402]  51.62 190.64 180 top
PC802  -  [C_0402]  46.8 187.34 180 top
PC803  -  [C_0603]  129.78 172.03 270 top
PC804  -  [C_0402]  57.26 186.88 90 top
PC805  -  [C_0402]  46.85 188.4 90 top
PC806  -  [C_0402]  128.63 172.05 270 top
PC807  -  [C_0805]  159.75 167.06 90 bottom
PC808  -  [C_0402]  74.53 172.17 270 top
PC809  -  [C_0402]  121.17 173.75 0 top
PC810  -  [C_0402]  73.52 172.17 270 top
PC811  -  [C_0603]  133.52 187.85 180 bottom
PC812  -  [C_0402]  66.28 171.39 90 top
PC813  -  [C_0603]  149.21 162.13 270 top
PC814  -  [C_0402]  165.72 169.25 270 top
PC815  -  [C_0603]  150.48 162.13 270 top
PC816  -  [C_0603]  157.65 164.35 0 top
PC817  -  [C_0402]  157.84 165.44 0 top
PC818  -  [C_0402]  37.36 170.99 90 top
PC900  -  [C_0805]  144.64 101.32 270 bottom
PC901  -  [C_0805]  146.41 101.32 270 bottom
PC902  -  [C_0805]  148.45 101.32 270 bottom
PC903  -  [C_0805]  150.48 101.32 270 bottom
PC904  -  [C_0805]  152.51 101.32 270 bottom
PC905  -  [C_D1]  155.68 120.08 90 top
PC906  -  [C_D1]  140.83 119.83 90 bottom
PC907  -  [C_D1]  151.8 96.41 0 top
PC908  -  [C_D1]  155.68 119.83 90 bottom
PC909  -  [C_0805]  154.54 101.32 270 bottom
PC910  -  [C_0805]  156.57 101.32 270 bottom
PC911  -  [C_0805]  158.61 101.32 270 bottom
PC912  -  [C_0805]  160.64 101.32 270 bottom
PC913  -  [C_0805]  162.67 101.32 270 bottom
PC914  -  [C_0805]  164.7 101.32 270 bottom
PC915  -  [C_D1]  148.06 124.65 90 bottom
PC916  -  [C_D1]  140.83 120.08 90 top
PC917  -  [C_0805]  152.26 119.43 90 top
PC918  -  [C_0805]  146.92 119.43 90 top
PC919  -  [C_0805]  144.25 119.43 90 top
PC920  -  [C_0805]  149.72 119.43 90 top
PC921  -  [C_0805]  144.64 101.32 270 top
PC922  -  [C_0805]  164.7 101.32 270 top
PC923  -  [C_0805]  162.67 101.32 270 top
PC924  -  [C_0805]  160.64 101.32 270 top
PC925  -  [C_0805]  158.61 101.32 270 top
PC926  -  [C_0805]  156.57 101.32 270 top
PC927  -  [C_0402]  220.91 131.29 90 top
PC928  -  [C_0402]  220.85 129.13 90 top
PC929  -  [C_0402]  221.1 127.22 270 top
PC930  -  [C_0402]  220.98 133.13 90 top
PC931  -  [C_0402]  219.96 130.16 270 top
PC932  -  [C_0402]  220.09 133.13 90 top
PC933  -  [C_0402]  220.01 132.22 270 top
PC934  -  [C_0402]  220 128.26 270 top
PC935  -  [C_0805]  154.54 101.32 270 top
PC936  -  [C_0805]  152.51 101.32 270 top
PC937  -  [C_0805]  150.48 101.32 270 top
PC938  -  [C_0805]  148.45 101.32 270 top
PC939  -  [C_0805]  146.41 101.32 270 top
PC940  -  [C_0805]  144.25 119.43 90 bottom
PC941  -  [C_0805]  146.92 119.43 90 bottom
PC942  -  [C_0805]  149.72 119.43 90 bottom
PC943  -  [C_0805]  152.26 119.43 90 bottom
PC944  -  [C_0402]  222.04 133.19 270 top
PC945  -  [C_0402]  222.07 131.15 270 top
PC946  -  [C_0402]  224.04 129.21 270 top
PC947  -  [C_0402]  222.07 129.2 270 top
PC948  -  [C_0402]  222.08 127.2 270 top
PC949  -  [C_0402]  264.78 149.44 270 bottom
PC950  -  [C_0402]  224.01 131.15 270 top
PC951  -  [C_0402]  226.05 131.14 270 top
PC952  -  [C_0402]  226.03 133.18 270 top
PC953  -  [C_0402]  225.02 127.22 270 top
PC954  -  [C_0402]  224.05 127.22 270 top
PC955  -  [C_0402]  222.09 135.17 270 top
PC956  -  [C_0402]  224.08 135.17 270 top
PC957  -  [C_0402]  263.76 149.44 270 bottom
PC958  -  [C_0402]  228.22 130.84 90 top
PC959  -  [C_0402]  228.09 134.12 270 top
PC960  -  [C_0402]  227.16 125.93 180 top
PC961  -  [C_0402]  263.51 166.05 90 bottom
PC962  -  [C_0402]  264.52 166.05 90 bottom
PC963  -  [C_0603]  262.49 149.43 270 bottom
PC964  -  [C_0603]  260.97 166.06 90 bottom
PC965  -  [C_0603]  262.24 166.06 90 bottom
PC966  -  [C_0603]  261.22 149.43 270 bottom
PC967  -  [C_0402]  226.25 128.76 180 top
PC968  -  [C_0402]  224.02 133.21 270 top
PC969  -  [C_0402]  218.06 133.21 270 top
PC970  -  [C_D2]  256.68 162.42 90 bottom
PC971  -  [C_D2]  251.84 162.42 90 bottom
PCV172  -  [C_0402]  218 135.26 90 top
PCV174  -  [C_0402]  218.03 131.18 270 top
PCV175  -  [C_0402]  219.19 135.18 0 top
PCV183  -  [C_0603]  216.66 136.38 90 top
PD1  -  [IP4223CZ6_SO6]  240.28 62.71 180 top
PD2  -  [TVNST52302AB0_SOT523-3]  118.49 185.9 90 top
PD3  -  [BAS40-05W_SC70-3]  325.17 154.4 0 bottom
PD4  -  [TVNST52302AB0_SOT523-3]  116.86 184.72 180 top
PD7  -  [SDMK0340L-7-F_SOD323-2]  113.17 185.41 180 top
PD700  -  [ES2AA-13-F_SMA2]  125.59 170.54 270 bottom
PD701  -  [RB717F_SOT323-3]  88.69 168.1 90 top
PD702  -  [BAT54HT1G_SOD323-2]  82.74 181.41 270 top
PD800  -  [PDS5100H-13_POWERDI5-3]  112.44 180.1 0 bottom
PD801  -  [PDS5100H-13_POWERDI5-3]  245.54 87.77 0 top
PD802  -  [SDMK0340L-7-F_SOD323-2]  246.81 91.07 0 top
PD803  -  [SDMK0340L-7-F_SOD323-2]  237.35 81.49 90 top
PD804  -  [SDMK0340L-7-F_SOD323-2]  232.84 83.32 0 top
PD805  -  [SDMK0340L-7-F_SOD323-2]  134.6 173.69 90 top
PD806  -  [PDS5100H-13_POWERDI5-3]  125.86 178.32 0 bottom
PD807  -  [SDMK0340L-7-F_SOD323-2]  132.82 173.69 90 top
PD808  -  [PDS5100H-13_POWERDI5-3]  152.32 189.12 0 top
PD809  -  [SDMK0340L-7-F_SOD323-2]  120.31 173.37 180 bottom
PD811  -  [SDMK0340L-7-F_SOD323-2]  117.91 165.62 0 bottom
PD812  -  [SDMK0340L-7-F_SOD323-2]  120.31 171.46 180 bottom
PD814  -  [RB717F_SOT323-3]  68.87 174.25 180 top
PD816  -  [RB717F_SOT323-3]  45.12 173.29 270 top
PD817  -  [RB717F_SOT323-3]  151.21 176.06 90 top
PD818  -  [SDMK0340L-7-F_SOD323-2]  57.77 181.38 90 bottom
PD819  -  [SDMK0340L-7-F_SOD323-2]  67.67 176.12 90 top
PD820  -  [SDMK0340L-7-F_SOD323-2]  144.89 174.63 90 top
PD821  -  [SDMK0340L-7-F_SOD323-2]  42.03 169.96 180 top
PH500  -  [R_0402]  135.49 139.64 90 top
PH501  -  [R_0402]  137.27 132.65 90 bottom
PH600  -  [R_0402]  294.42 145.58 0 top
PH601  -  [R_0402]  289.07 146.94 180 bottom
PJP1  -  [JUMP_43X79]  239.89 77.14 270 top
PJP2  -  [JUMP_43X39]  30.34 195.52 90 top
PJP3  -  [JUMP_43X79]  114.62 40.27 0 top
PJP4  -  [JUMP_43X118]  142.17 172.42 270 top
PJP5  -  [JUMP_43X118]  149.36 69.55 90 top
PJP6  -  [JUMP_43X118]  166.4 69.74 90 top
PJP7  -  [JUMP_43X79]  121.28 3.93 90 top
PJP53  -  [JUMP_43X39]  116.7 18 270 bottom
PJP60  -  [JUMP_43X79]  334.76 170.29 0 bottom
PJP61  -  [JUMP_43X39]  296.53 122.87 90 top
PJP62  -  [JUMP_43X39]  335.34 159.78 180 top
PJP63  -  [JUMP_43X39]  279.76 51.75 90 top
PJP64  -  [JUMP_43X39]  115.88 47.89 180 top
PJP65  -  [JUMP_43X39]  293.02 100.22 0 top
PJP66  -  [JUMP_43X39]  327.06 211.98 0 top
PJP67  -  [JUMP_43X39]  180.96 127.44 90 bottom
PJP68  -  [JUMP_43X39]  327.06 209.69 0 top
PJP69  -  [JUMP_43X39]  335.64 193.89 270 top
PJP70  -  [JUMP_43X39]  325.99 191.35 270 top
PJP71  -  [JUMP_43X39]  45.53 182 180 bottom
PJP72  -  [JUMP_43X39]  45.53 179.72 180 bottom
PJP73  -  [JUMP_43X39]  338.78 187.83 90 top
PJP74  -  [JUMP_43X39]  346.48 189.43 90 top
PJP80  -  [JUMP_43X39]  346.93 174.84 180 bottom
PJP81  -  [JUMP_43X39]  342.17 178.66 270 bottom
PJP100  -  [JUMP_43X118]  131.94 13.81 90 top
PJP101  -  [JUMP_43X118]  167.17 4.63 270 bottom
PJP102  -  [JUMP_43X118]  137.27 13.81 90 top
PJP103  -  [JUMP_43X118]  172.46 4.61 270 bottom
PJP104  -  [JUMP_43X118]  170.89 7.52 180 top
PJP200  -  [JUMP_43X118]  200.01 18.64 90 top
PJP201  -  [JUMP_43X39]  209.61 9.54 180 top
PJP202  -  [JUMP_43X39]  203.36 11.57 0 top
PJP203  -  [JUMP_43X118]  182.48 17.45 270 top
PJP204  -  [JUMP_43X118]  177.15 17.45 270 top
PJP300  -  [JUMP_43X79]  223.63 11.23 270 top
PJP301  -  [JUMP_43X79]  215.5 17.2 270 bottom
PJP302  -  [JUMP_43X79]  219.57 17.2 270 bottom
PJP400  -  [JUMP_43X79]  231.69 100.07 270 top
PJP401  -  [JUMP_43X79]  234.76 100.47 0 top
PJP500  -  [JUMP_43X118]  144.74 156.61 270 top
PJP600  -  [JUMP_43X118]  292.84 172.44 270 top
PJP601  -  [JUMP_43X118]  268.38 152.54 180 bottom
PJP602  -  [JUMP_43X39]  308.34 164.07 90 top
PJP603  -  [JUMP_43X118]  268.38 163.72 180 bottom
PJP604  -  [JUMP_43X118]  268.38 158.13 180 bottom
PJP609  -  [JUMP_43X79]  196.2 99.67 90 top
PJP610  -  [JUMP_43X79]  190.1 98.99 270 top
PJP611  -  [JUMP_43X79]  288.87 132.47 0 top
PJP612  -  [JUMP_43X79]  288.02 141.91 270 top
PJP700  -  [JUMP_43X118]  97.92 186.96 180 top
PJP701  -  [JUMP_43X39]  76.77 182.89 180 bottom
PJPDC1  -  [JESS_UCNR2451M005-0_5P]  137.44 171.17 0 bottom
PL1  -  [TAIYO_FBMJ4516HS720NT_2P]  239.89 74.63 90 top
PL2  -  [TAIYO_FBMJ4516HS720NT_2P]  124.75 184.54 0 bottom
PL3  -  [TAIYO_FBMJ4516HS720NT_2P]  124.73 182.06 0 bottom
PL4  -  [MURAT_BLM18BD102SN1D_L0603_2P]  151.33 168.92 180 bottom
PL5  -  [KC_FBMA-L11-453215800LMA90T_2P]  137.65 174.12 270 top
PL101  -  [TOKO_FDSD0630-H-2R2M-P3_2P]  135.26 6.62 0 bottom
PL102  -  [CYNTE_PCMC063T-2R2MN_2P]  157.55 5.8 0 bottom
PL103  -  [MAGLA_MMD-05CZ-1R0M-M7L_2P]  172.4 7.51 180 top
PL201  -  [TOKO_FDUE1040D-H-1R0M-P3_2P]  188.3 7.38 0 bottom
PL301  -  [TOKO_FDSD0630-H-1R0M-P3_2P]  231.64 8.52 180 bottom
PL401  -  [TAIYO_NRS4018T1R0NDGJ_2P]  238.34 104.79 0 top
PL501  -  [TOKO_FDUE0640J-H_4P]  154.41 129.36 90 bottom
PL502  -  [TOKO_FDUE0640J-H_4P]  128.38 129.32 90 bottom
PL503  -  [TOKO_FDUE0640J-H_4P]  141.59 129.36 90 bottom
PL504  -  [KC_FBMA-L11-453215800LMA90T_2P]  144.83 154.22 90 top
PL600  -  [TOKO_FDUE0640J-H_4P]  282.46 163.46 0 bottom
PL601  -  [TOKO_FDUE0640J-H_4P]  282.46 153.56 0 bottom
PL603  -  [TOKO_FDSD0420-H-1R0M-P3T_2P]  194.55 93.87 180 top
PL604  -  [TAIYO_NRS4018T1R0NDGJ_2P]  282.43 138.06 0 top
PL700  -  [TOKO_FDVE1040-H-2R2M-P3_2P]  104.12 174.18 90 bottom
PL701  -  [MAGLA_MMD-05CZ-1R0M-M7L_2P]  95.34 187.08 0 top
PQ1  -  [FDV301N-G_SOT23-3]  151.49 171.06 180 bottom
PQ2  -  [MMST3904-7-F_SOT323-3]  148.19 172.54 0 bottom
PQ3  -  [TP0610K-T1-E3_SOT23-3]  125.2 2.91 0 top
PQ4  -  [FDS6679AZ-G_SO8]  134.52 164.35 90 top
PQ5  -  [SSM3K7002FU_SC70-3]  128.38 8.33 180 top
PQ6  -  [IMD2AT-108_SC74-6]  138.53 158.96 270 top
PQ7  -  [DMG2301U-7_SOT23-3]  107.42 184.85 180 top
PQ101  -  [SIS412DN-T1-GE3_POWERPAK8-5]  139.58 3.33 0 top
PQ102  -  [SIS412DN-T1-GE3_POWERPAK8-5]  163.2 4.6 0 top
PQ103  -  [SIS472DN-T1_POWERPAK1212-8-5]  137.5 6.22 180 top
PQ104  -  [SIS472DN-T1_POWERPAK1212-8-5]  161.12 7.61 180 top
PQ201  -  [SIR472DP-T1-GE3_POWERPAK8-5]  196.32 6.36 0 top
PQ203  -  [SIRA06DP-T1-GE_POWERPAKSO-8-5]  194.04 11.7 180 top
PQ301  -  [SIS412DN-T1-GE3_POWERPAK8-5]  231.99 8.55 90 top
PQ303  -  [SIS472DN-T1_POWERPAK1212-8-5]  229.24 6.72 270 top
PQ501  -  [SIR472DP-T1-GE3_POWERPAK8-5]  149.59 137.04 0 top
PQ502  -  [SIR472DP-T1-GE3_POWERPAK8-5]  155.18 137.04 0 top
PQ503  -  [SIRA06DP-T1-GE_POWERPAKSO-8-5]  155.56 146.7 0 bottom
PQ504  -  [SIRA06DP-T1-GE_POWERPAKSO-8-5]  150.1 146.7 0 bottom
PQ505  -  [SIR472DP-T1-GE3_POWERPAK8-5]  123.68 137.17 0 top
PQ506  -  [SIR472DP-T1-GE3_POWERPAK8-5]  129.27 137.17 0 top
PQ507  -  [SIRA06DP-T1-GE_POWERPAKSO-8-5]  129.19 146.7 0 bottom
PQ508  -  [SIRA06DP-T1-GE_POWERPAKSO-8-5]  123.76 146.7 0 bottom
PQ509  -  [SIR472DP-T1-GE3_POWERPAK8-5]  136.76 137.17 0 top
PQ510  -  [SIR472DP-T1-GE3_POWERPAK8-5]  142.35 137.17 0 top
PQ511  -  [SIRA06DP-T1-GE_POWERPAKSO-8-5]  142.48 146.7 0 bottom
PQ512  -  [SIRA06DP-T1-GE_POWERPAKSO-8-5]  137.02 146.7 0 bottom
PQ600  -  [SIR472DP-T1-GE3_POWERPAK8-5]  290.3 169.15 270 top
PQ601  -  [SIR472DP-T1-GE3_POWERPAK8-5]  290.3 163.06 270 top
PQ602  -  [SIRA06DP-T1-GE_POWERPAKSO-8-5]  299.83 164.22 270 bottom
PQ603  -  [SIRA06DP-T1-GE_POWERPAKSO-8-5]  299.83 169.81 270 bottom
PQ604  -  [SIR472DP-T1-GE3_POWERPAK8-5]  290.3 150.79 270 top
PQ605  -  [SIR472DP-T1-GE3_POWERPAK8-5]  290.3 156.91 270 top
PQ606  -  [SIRA06DP-T1-GE_POWERPAKSO-8-5]  299.96 158.25 270 bottom
PQ607  -  [SIRA06DP-T1-GE_POWERPAKSO-8-5]  299.96 152.67 270 bottom
PQ610  -  [DMN65D8LW-7_SOT323-3]  320.82 158.76 90 bottom
PQ700  -  [SI4835DDY-T1-GE3_SO8]  127.24 171.44 180 top
PQ701  -  [NTR4502PT1G_SOT23-3]  112.89 169.46 180 top
PQ702  -  [NTR4502PT1G_SOT23-3]  108.82 169.58 180 top
PQ703  -  [SI3993CDV-T1-GE3_TSOP6]  112.19 160.41 0 top
PQ704  -  [SIR472DP-T1-GE3_POWERPAK8-5]  97.77 182.58 180 bottom
PQ705  -  [SIR472DP-T1-GE3_POWERPAK8-5]  91.58 182.58 180 bottom
PQ706  -  [SIRA14DP-T1GE3_POWERPAK-SO8-5]  92.06 175.27 180 bottom
PQ707  -  [DMN66D0LDW-7_SOT363-6]  93.44 158.64 0 top
PQ709  -  [DMN65D8LW-7_SOT323-3]  74.53 176.35 0 top
PQ710  -  [DMN65D8LW-7_SOT323-3]  86.62 161.64 180 top
PQ711  -  [SIRA14DP-T1GE3_POWERPAK-SO8-5]  97.82 175.27 180 bottom
PQ800  -  [SI4835DDY-T1-GE3_SO8]  110.88 182 270 top
PQ801  -  [NTR4502PT1G_SOT23-3]  239.1 92.98 270 top
PQ802  -  [DMN66D0LDW-7_SOT363-6]  53.31 183.17 0 top
PQ803  -  [SI4835BDY-T1-E3_SO8]  243.59 84.59 270 top
PQ804  -  [FDS6679AZ_SO8]  243.66 79.01 270 top
PQ805  -  [DMN66D0LDW-7_SOT363-6]  56.1 183.17 0 top
PQ806  -  [DMN66D0LDW-7_SOT363-6]  53.56 187.49 0 top
PQ807  -  [DMN66D0LDW-7_SOT363-6]  239.02 88.55 270 top
PQ808  -  [2N7002DW-T-R7_SOT363-6]  240.54 83.3 180 top
PQ809  -  [SI4835DDY-T1-GE3_SO8]  124.34 180.1 270 top
PQ810  -  [FDS6679AZ-G_SO8]  150.69 185.94 270 top
PQ811  -  [FDS6679AZ-G_SO8]  134.52 182.13 90 top
PQ812  -  [DMN66D0LDW-7_SOT363-6]  120.47 167.81 180 bottom
PQ813  -  [DMN66D0LDW-7_SOT363-6]  54.75 176.3 270 top
PQ814  -  [NTR4502PT1G_SOT23-3]  48.98 173.62 270 top
PQ815  -  [FDS6679AZ-G_SO8]  118.09 176.5 0 top
PQ816  -  [AO3402_SOT23-3]  119.92 169.2 180 top
PQ817  -  [DMN65D8LW-7_SOT323-3]  71.86 176.58 0 top
PQ818  -  [DMN65D8LW-7_SOT323-3]  60.43 171.3 180 top
PQ819  -  [DMN66D0LDW-7_SOT363-6]  64.35 175 90 top
PQ820  -  [NTR4502PT1G_SOT23-3]  39.84 172.16 0 top
PQ821  -  [DMN66D0LDW-7_SOT363-6]  56.47 177.8 90 top
PQ822  -  [NTR4502PT1G_SOT23-3]  48.98 177.94 270 top
PQ823  -  [NTR4502PT1G_SOT23-3]  157.36 178.19 90 top
PQ824  -  [DMN66D0LDW-7_SOT363-6]  157.73 174.28 180 bottom
PQ825  -  [RHU002N06_SOT323-3]  169.24 169.81 270 top
PQ826  -  [FDS6679AZ-G_SO8]  121.9 176.5 180 bottom
PQ827  -  [RHU002N06_SOT323-3]  55.01 172.29 180 top
PQ828  -  [DMG2301U-7_SOT23-3]  148.51 179.39 270 top
PQ829  -  [RHU002N06_SOT323-3]  148.01 176.66 90 top
PQ830  -  [RHU002N06_SOT323-3]  34.07 175.4 180 top
PQ910  -  [2N7002DW-T-R7_SOT363-6]  158.76 171.45 90 bottom
PR1  -  [R_0402]  323.35 155.36 90 bottom
PR2  -  [R_0402]  240.27 58.23 180 top
PR3  -  [R_0402]  242.48 62.75 0 top
PR4  -  [R_0402]  242.48 63.77 0 top
PR5  -  [R_0402]  237.57 58.23 0 top
PR6  -  [R_0402]  115.68 185.64 270 bottom
PR7  -  [R_0402]  122.41 184.91 270 bottom
PR8  -  [R_0402]  121.52 184.92 270 bottom
PR9  -  [R_0402]  120.63 184.92 270 bottom
PR10  -  [R_0402]  154.16 171.01 90 bottom
PR11  -  [R_0402]  155.18 173.82 270 bottom
PR12  -  [R_0402]  154.16 172.91 90 bottom
PR13  -  [R_0402]  148.57 168.47 90 bottom
PR14  -  [R_0402]  150.22 175.07 90 bottom
PR15  -  [R_0402]  147.43 169.38 270 bottom
PR16  -  [R_0402]  149.08 175.98 270 bottom
PR17  -  [R_0402]  125.01 8.27 0 top
PR18  -  [R_0402]  132.65 171.34 180 top
PR19  -  [R_0402]  104.05 154.44 0 bottom
PR20  -  [R_0402]  122.03 164.3 270 top
PR21  -  [R_0402]  128.96 4.33 180 top
PR22  -  [R_0805]  137.44 164.48 0 top
PR23  -  [R_0402]  131.5 168.67 180 bottom
PR24  -  [R_0402]  128.96 5.22 180 top
PR25  -  [R_0402]  131.5 167.53 180 bottom
PR26  -  [R0402_0OHM]  107.37 180.03 180 top
PR100  -  [R_0402]  148.19 1.97 90 bottom
PR101  -  [R_0402]  151.24 1.97 90 bottom
PR102  -  [R_0402]  149.21 1.97 90 bottom
PR103  -  [R0402_0OHM]  150.22 2.88 270 bottom
PR104  -  [R_0402]  152.26 1.97 90 bottom
PR105  -  [R_0402]  147.18 2.88 270 bottom
PR106  -  [R_0402]  153.27 2.88 270 bottom
PR107  -  [R_0603]  153.78 7.58 0 bottom
PR108  -  [R_0603]  144.95 8.78 0 bottom
PR109  -  [R_1206]  132.44 4.9 90 top
PR110  -  [R0402_0OHM]  145.19 2.68 0 bottom
PR111  -  [R_0402]  151.54 6.06 0 top
PR112  -  [R_1206]  157.21 4.9 90 top
PR118  -  [R0402_0OHM]  145.19 5.22 0 bottom
PR119  -  [R_0402]  146.11 6.24 180 bottom
PR200  -  [R_0603]  205.15 13.86 0 top
PR201  -  [R_0402]  212.2 17.72 90 top
PR202  -  [R_1206]  196.77 13.73 180 bottom
PR203  -  [R_0603]  209.53 17.73 90 top
PR204  -  [R_0402]  214.28 10.05 0 top
PR205  -  [R_0402]  215.2 15.13 180 top
PR206  -  [R_0402]  215.2 13.09 180 top
PR207  -  [R_0402]  212.96 9.33 90 top
PR208  -  [R0402_0OHM]  215.2 12.08 180 top
PR209  -  [R_0402]  215.2 16.14 180 top
PR210  -  [R0402_0OHM]  269.73 41.6 270 top
PR300  -  [R_0402]  236.08 4.91 270 top
PR301  -  [R_0603]  237.6 12.2 90 top
PR302  -  [R_0402]  237.09 4 90 top
PR303  -  [R_0402]  238.11 4 90 top
PR304  -  [R_1206]  231.57 3.44 180 bottom
PR305  -  [R_0402]  243.19 4.91 270 top
PR306  -  [R_0402]  242.17 3.99 90 top
PR307  -  [R_0402]  241.16 4 90 top
PR308  -  [R0402_0OHM]  240.14 4 90 top
PR400  -  [R_0402]  236.33 108.29 270 top
PR401  -  [R_0805]  239.19 108.34 0 top
PR402  -  [R_0402]  230.79 106.06 0 top
PR403  -  [R_0402]  235.31 108.29 270 top
PR404  -  [R_0402]  233.28 107.38 90 top
PR405  -  [R_0402]  231.25 107.38 90 top
PR406  -  [R0402_0OHM]  234.3 108.29 270 top
PR500  -  [R_0402]  119.22 150.02 270 bottom
PR501  -  [R0402_0OHM]  157.21 155.26 90 top
PR502  -  [R_0603]  163.69 153.49 90 top
PR503  -  [R_0402]  117.19 150.02 270 bottom
PR504  -  [R_0402]  115.63 150.89 180 bottom
PR505  -  [R0402_0OHM]  120.24 149.11 90 bottom
PR506  -  [R0402_0OHM]  118.21 149.11 90 bottom
PR507  -  [R_0402]  121.01 153.63 270 top
PR508  -  [R0402_0OHM]  116.18 149.11 90 bottom
PR509  -  [R_0402]  120 153.63 270 top
PR510  -  [R_0603]  131.62 160.29 0 bottom
PR511  -  [R0402_0OHM]  114.71 151.9 0 top
PR512  -  [R_0402]  118.98 153.63 270 top
PR513  -  [R_1206]  148.19 144.22 90 bottom
PR514  -  [R_0603]  131.62 159.02 0 bottom
PR515  -  [R_0402]  131.86 157.49 0 bottom
PR516  -  [R_0402]  129.57 159.27 0 bottom
PR518  -  [R_0402]  129.57 160.29 0 bottom
PR519  -  [R_0402]  113.34 152.92 180 bottom
PR520  -  [R0402_0OHM]  124.87 152.92 0 top
PR521  -  [R_0402]  115.63 153.94 180 top
PR522  -  [R0402_0OHM]  114.71 152.92 0 bottom
PR523  -  [R_0402]  125.13 152.67 0 bottom
PR524  -  [R0402_0OHM]  114.71 154.95 0 bottom
PR525  -  [R_0402]  135.49 142.33 270 top
PR526  -  [R0402_0OHM]  125.13 156.73 0 bottom
PR527  -  [R_0402]  112.43 154.95 0 bottom
PR528  -  [R_0402]  134.6 139.64 90 top
PR529  -  [R_0402]  119.49 155.89 90 top
PR530  -  [R_0402]  124.82 159.32 90 bottom
PR531  -  [R_0402]  117.2 160.49 270 bottom
PR532  -  [R_0402]  115.63 158 180 bottom
PR533  -  [R_0402]  114.71 160.03 0 bottom
PR534  -  [R_0603]  122.16 148.67 90 bottom
PR535  -  [R_0402]  121.27 159.58 90 top
PR536  -  [R_0603]  120.12 145.81 270 bottom
PR537  -  [R_0402]  114.71 158 0 top
PR538  -  [R_0603]  118.85 144.41 90 bottom
PR539  -  [R_0402]  114.71 156.98 0 bottom
PR540  -  [R0402_0OHM]  116.19 162.9 270 bottom
PR541  -  [R_1206]  121.9 144.22 90 bottom
PR542  -  [R_0402]  114.71 156.98 0 top
PR543  -  [R_0402]  114.71 159.02 0 bottom
PR544  -  [R_0402]  117.79 144.4 90 bottom
PR545  -  [R_0402]  119.24 162.9 270 bottom
PR546  -  [R_0402]  118.85 146.75 90 top
PR547  -  [R_0402]  118.85 146.75 90 bottom
PR548  -  [R0402_0OHM]  122.59 162.19 0 bottom
PR549  -  [R_0402]  124.82 160.24 270 top
PR550  -  [R_0603]  126.54 155.46 180 bottom
PR551  -  [R_0402]  122.41 160.49 270 top
PR552  -  [R_0603]  133.52 156.35 0 bottom
PR553  -  [R_0603]  134.92 155.08 180 bottom
PR554  -  [R_1206]  134.98 144.22 90 bottom
PR555  -  [R_0402]  132.57 155 90 bottom
PR556  -  [R_0402]  134.93 153.81 180 bottom
PR557  -  [R_0402]  132.57 155 90 top
PR558  -  [R_0402]  120.39 146.81 90 bottom
PR600  -  [R0402_0OHM]  312.95 168.74 270 bottom
PR601  -  [R_0402]  313.16 171.03 270 bottom
PR602  -  [R_0402]  312.28 170.12 90 bottom
PR603  -  [R_0402]  310.37 171.03 270 bottom
PR604  -  [R_0402]  311.26 170.12 90 bottom
PR605  -  [R_0402]  310.24 168.74 270 bottom
PR606  -  [R_0402]  310.24 167.83 90 top
PR607  -  [R_0402]  312.91 168.74 270 top
PR608  -  [R_0402]  308.85 170.12 90 bottom
PR609  -  [R_0402]  307.96 171.03 270 bottom
PR610  -  [R_0402]  306.69 168.74 270 bottom
PR611  -  [R_0402]  306.69 167.83 90 top
PR612  -  [R_0402]  305.8 168.74 270 bottom
PR613  -  [R_0402]  305.8 167.83 90 top
PR614  -  [R_0603]  303.2 165.05 0 bottom
PR615  -  [R_0402]  312.02 168.74 270 bottom
PR616  -  [R_0402]  311.39 164.4 90 top
PR617  -  [R0402_0OHM]  312.28 171.03 270 top
PR618  -  [R0402_0OHM]  310.37 171.03 270 top
PR619  -  [R_0402]  306.18 151.83 90 bottom
